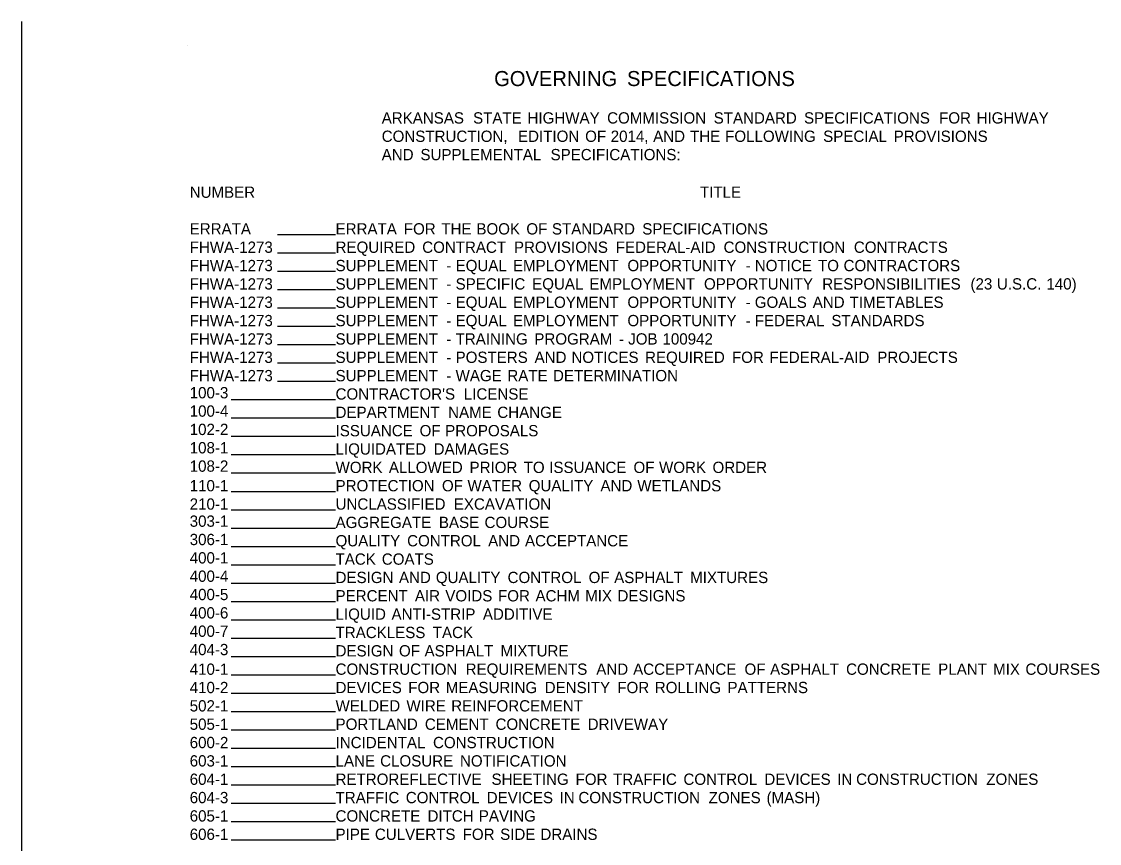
# Model space of a CAD drawing. Extents: x 1.5 to 33, y 0.6 to 21.4.
# Drawn here: x 1.52 to 15.26, y 10.94 to 21.42 of the extents above; entities that cross this region are included whole.
import ezdxf

# ---------------------------------------------------------------- set-up
doc = ezdxf.new("R2010")
doc.units = 0
doc.layers.add('Default', color=7, linetype='Continuous')

msp = doc.modelspace()

# ---------------------------------------------------------------- linework, layer by layer
at = {"layer": 'Default'}
for p, q in [((1.516, 21.423), (1.516, 0.577)), ((3.636, 21.112), (3.636, 21.112)), ((4.78, 18.707), (5.52, 18.707)), ((4.78, 18.473), (5.52, 18.473)), ((4.78, 18.239), (5.52, 18.239)), ((4.78, 18.005), (5.52, 18.005)), ((4.78, 17.771), (5.52, 17.771)), ((4.78, 17.537), (5.52, 17.537)), ((4.78, 17.303), (5.52, 17.303)), ((4.78, 17.069), (5.52, 17.069)), ((4.78, 16.835), (5.52, 16.835)), ((4.188, 16.601), (5.52, 16.601)), ((4.188, 16.367), (5.52, 16.367)), ((4.188, 16.133), (5.52, 16.133)), ((4.188, 15.899), (5.52, 15.899)), ((4.188, 15.665), (5.52, 15.665)), ((4.188, 15.431), (5.52, 15.431)), ((4.188, 15.197), (5.52, 15.197)), ((4.188, 14.963), (5.52, 14.963)), ((4.188, 14.729), (5.52, 14.729)), ((4.188, 14.495), (5.52, 14.495)), ((4.188, 14.261), (5.52, 14.261)), ((4.188, 14.027), (5.52, 14.027)), ((4.188, 13.793), (5.52, 13.793)), ((4.188, 13.559), (5.52, 13.559)), ((4.188, 13.325), (5.52, 13.325)), ((4.188, 13.091), (5.52, 13.091)), ((4.188, 12.857), (5.52, 12.857)), ((4.188, 12.623), (5.52, 12.623)), ((4.188, 12.389), (5.52, 12.389)), ((4.188, 12.155), (5.52, 12.155)), ((4.188, 11.921), (5.52, 11.921)), ((4.188, 11.687), (5.52, 11.687)), ((4.188, 11.453), (5.52, 11.453)), ((4.188, 11.219), (5.52, 11.219)), ((4.188, 10.985), (5.52, 10.985))]:
    msp.add_line(p, q, dxfattribs=at)

# ---------------------------------------------------------------- texts
for s, height, p in [('GOVERNING', 0.192, (7.542, 20.6)), (' SPECIFICATIONS', 0.192, (9.165, 20.6)), ('           ARKANSAS', 0.144, (5.52, 20.122)), (' STATE', 0.144, (7.22, 20.122)), (' HIGHWAY', 0.144, (7.914, 20.122)), (' COMMISSION', 0.144, (8.929, 20.122)), (' STANDARD', 0.144, (10.288, 20.122)), (' SPECIFICATIONS', 0.144, (11.44, 20.122)), (' FOR', 0.144, (13.162, 20.122)), (' HIGHWAY', 0.144, (13.64, 20.122)), ('           CONSTRUCTION,', 0.144, (5.52, 19.888)), (' EDITION', 0.144, (7.793, 19.888)), (' OF', 0.144, (8.649, 19.888)), (' 2014,', 0.144, (8.975, 19.888)), (' AND', 0.144, (9.516, 19.888)), (' THE', 0.144, (9.986, 19.888)), (' FOLLOWING', 0.144, (10.434, 19.888)), (' SPECIAL', 0.144, (11.684, 19.888)), (' PROVISIONS', 0.144, (12.583, 19.888)), ('           AND', 0.144, (5.52, 19.654)), (' SUPPLEMENTAL', 0.144, (6.549, 19.654)), (' SPECIFICATIONS:', 0.144, (8.208, 19.654)), ('NUMBER', 0.144, (3.66, 19.175)), ('TITLE', 0.144, (10.166, 19.175)), ('ERRATA', 0.144, (3.66, 18.707)), ('ERRATA', 0.144, (5.52, 18.707)), (' FOR', 0.144, (6.337, 18.707)), (' THE', 0.144, (6.815, 18.707)), (' BOOK', 0.144, (7.262, 18.707)), (' OF', 0.144, (7.899, 18.707)), (' STANDARD', 0.144, (8.225, 18.707)), (' SPECIFICATIONS', 0.144, (9.377, 18.707)), ('FHWA-1273', 0.144, (3.66, 18.473)), ('REQUIRED', 0.144, (5.52, 18.473)), (' CONTRACT', 0.144, (6.571, 18.473)), (' PROVISIONS', 0.144, (7.741, 18.473)), (' FEDERAL-AID', 0.144, (9.039, 18.473)), (' CONSTRUCTION', 0.144, (10.414, 18.473)), (' CONTRACTS', 0.144, (12.075, 18.473)), ('FHWA-1273', 0.144, (3.66, 18.239)), ('SUPPLEMENT', 0.144, (5.52, 18.239)), (' -', 0.144, (6.88, 18.239)), (' EQUAL', 0.144, (6.997, 18.239)), (' EMPLOYMENT', 0.144, (7.728, 18.239)), (' OPPORTUNITY', 0.144, (9.188, 18.239)), (' -', 0.144, (10.696, 18.239)), (' NOTICE', 0.144, (10.812, 18.239)), (' TO', 0.144, (11.618, 18.239)), (' CONTRACTORS', 0.144, (11.944, 18.239)), ('FHWA-1273', 0.144, (3.66, 18.005)), ('SUPPLEMENT', 0.144, (5.52, 18.005)), (' SPECIFIC', 0.144, (6.997, 18.005)), (' EQUAL', 0.144, (7.973, 18.005)), (' EMPLOYMENT', 0.144, (8.703, 18.005)), (' OPPORTUNITY', 0.144, (10.164, 18.005)), (' RESPONSIBILITIES', 0.144, (11.672, 18.005)), (' (23', 0.144, (13.562, 18.005)), (' U.S.C.', 0.144, (13.899, 18.005)), (' 140)', 0.144, (14.53, 18.005)), (' -', 0.144, (6.88, 18.005)), ('FHWA-1273', 0.144, (3.66, 17.771)), ('SUPPLEMENT', 0.144, (5.52, 17.771)), (' EQUAL', 0.144, (6.997, 17.771)), (' EMPLOYMENT', 0.144, (7.728, 17.771)), (' OPPORTUNITY', 0.144, (9.188, 17.771)), (' GOALS', 0.144, (10.812, 17.771)), (' AND', 0.144, (11.551, 17.771)), (' TIMETABLES', 0.144, (12.021, 17.771)), (' -', 0.144, (6.88, 17.771)), (' -', 0.144, (10.696, 17.771)), ('FHWA-1273', 0.144, (3.66, 17.537)), ('SUPPLEMENT', 0.144, (5.52, 17.537)), (' -', 0.144, (6.88, 17.537)), (' EQUAL', 0.144, (6.997, 17.537)), (' EMPLOYMENT', 0.144, (7.728, 17.537)), (' OPPORTUNITY', 0.144, (9.188, 17.537)), (' -', 0.144, (10.696, 17.537)), (' FEDERAL', 0.144, (10.812, 17.537)), (' STANDARDS', 0.144, (11.789, 17.537)), ('FHWA-1273', 0.144, (3.66, 17.303)), ('SUPPLEMENT', 0.144, (5.52, 17.303)), (' -', 0.144, (6.88, 17.303)), (' TRAINING', 0.144, (6.997, 17.303)), (' PROGRAM', 0.144, (8.001, 17.303)), (' -', 0.144, (9.082, 17.303)), (' JOB', 0.144, (9.198, 17.303)), (' 100942', 0.144, (9.635, 17.303)), ('FHWA-1273', 0.144, (3.66, 17.069)), ('SUPPLEMENT', 0.144, (5.52, 17.069)), (' POSTERS', 0.144, (6.997, 17.069)), (' AND', 0.144, (8.004, 17.069)), (' NOTICES', 0.144, (8.474, 17.069)), (' REQUIRED', 0.144, (9.413, 17.069)), (' FOR', 0.144, (10.521, 17.069)), (' FEDERAL-AID', 0.144, (10.999, 17.069)), (' PROJECTS', 0.144, (12.374, 17.069)), (' -', 0.144, (6.88, 17.069)), ('FHWA-1273', 0.144, (3.66, 16.835)), ('SUPPLEMENT', 0.144, (5.52, 16.835)), (' WAGE', 0.144, (6.997, 16.835)), (' RATE', 0.144, (7.657, 16.835)), (' DETERMINATION', 0.144, (8.239, 16.835)), (' -', 0.144, (6.88, 16.835)), ('100-3', 0.144, (3.66, 16.617)), ("CONTRACTOR'S", 0.144, (5.52, 16.601)), (' LICENSE', 0.144, (7.102, 16.601)), ('100-4', 0.144, (3.66, 16.383)), ('DEPARTMENT', 0.144, (5.52, 16.367)), (' NAME', 0.144, (6.902, 16.367)), (' CHANGE', 0.144, (7.529, 16.367)), ('102-2', 0.144, (3.66, 16.149)), ('ISSUANCE', 0.144, (5.52, 16.133)), (' OF', 0.144, (6.538, 16.133)), (' PROPOSALS', 0.144, (6.864, 16.133)), ('108-1', 0.144, (3.66, 15.915)), ('LIQUIDATED', 0.144, (5.52, 15.899)), (' DAMAGES', 0.144, (6.717, 15.899)), ('108-2', 0.144, (3.66, 15.681)), ('WORK', 0.144, (5.52, 15.665)), (' ALLOWED', 0.144, (6.146, 15.665)), (' PRIOR', 0.144, (7.175, 15.665)), (' TO', 0.144, (7.865, 15.665)), (' ISSUANCE', 0.144, (8.191, 15.665)), (' OF', 0.144, (9.265, 15.665)), (' WORK', 0.144, (9.591, 15.665)), (' ORDER', 0.144, (10.273, 15.665)), ('110-1', 0.144, (3.66, 15.431)), ('PROTECTION', 0.144, (5.52, 15.431)), (' OF', 0.144, (6.823, 15.431)), (' WATER', 0.144, (7.149, 15.431)), (' QUALITY', 0.144, (7.929, 15.431)), (' AND', 0.144, (8.844, 15.431)), (' WETLANDS', 0.144, (9.314, 15.431)), ('210-1', 0.144, (3.66, 15.197)), ('UNCLASSIFIED', 0.144, (5.52, 15.197)), (' EXCAVATION', 0.144, (6.974, 15.197)), ('303-1', 0.144, (3.66, 14.979)), ('AGGREGATE', 0.144, (5.52, 14.963)), (' BASE', 0.144, (6.784, 14.963)), (' COURSE', 0.144, (7.366, 14.963)), ('306-1', 0.144, (3.66, 14.745)), ('QUALITY', 0.144, (5.52, 14.729)), (' CONTROL', 0.144, (6.379, 14.729)), (' AND', 0.144, (7.412, 14.729)), (' ACCEPTANCE', 0.144, (7.882, 14.729)), ('400-1', 0.144, (3.66, 14.511)), ('TACK', 0.144, (5.52, 14.495)), (' COATS', 0.144, (6.056, 14.495)), ('400-4', 0.144, (3.66, 14.277)), ('DESIGN', 0.144, (5.52, 14.261)), (' AND', 0.144, (6.275, 14.261)), (' QUALITY', 0.144, (6.745, 14.261)), (' CONTROL', 0.144, (7.66, 14.261)), (' OF', 0.144, (8.693, 14.261)), (' ASPHALT', 0.144, (9.019, 14.261)), (' MIXTURES', 0.144, (9.988, 14.261)), ('400-5', 0.144, (3.66, 14.043)), ('PERCENT', 0.144, (5.52, 14.027)), (' AIR', 0.144, (6.478, 14.027)), (' VOIDS', 0.144, (6.866, 14.027)), (' FOR', 0.144, (7.538, 14.027)), (' ACHM', 0.144, (8.016, 14.027)), (' MIX', 0.144, (8.649, 14.027)), (' DESIGNS', 0.144, (9.061, 14.027)), ('400-6', 0.144, (3.66, 13.809)), ('LIQUID', 0.144, (5.52, 13.793)), (' ANTI-STRIP', 0.144, (6.18, 13.793)), (' ADDITIVE', 0.144, (7.345, 13.793)), ('400-7', 0.144, (3.66, 13.575)), ('TRACKLESS', 0.144, (5.52, 13.559)), (' TACK', 0.144, (6.706, 13.559)), ('404-3', 0.144, (3.66, 13.341)), ('DESIGN', 0.144, (5.52, 13.325)), (' OF', 0.144, (6.275, 13.325)), (' ASPHALT', 0.144, (6.601, 13.325)), (' MIXTURE', 0.144, (7.57, 13.325)), ('410-1', 0.144, (3.66, 13.091)), ('CONSTRUCTION', 0.144, (5.52, 13.091)), (' REQUIREMENTS', 0.144, (7.125, 13.091)), (' AND', 0.144, (8.791, 13.091)), (' ACCEPTANCE', 0.144, (9.261, 13.091)), (' OF', 0.144, (10.681, 13.091)), (' ASPHALT', 0.144, (11.007, 13.091)), (' CONCRETE', 0.144, (11.976, 13.091)), (' PLANT', 0.144, (13.151, 13.091)), (' MIX', 0.144, (13.851, 13.091)), (' COURSES', 0.144, (14.263, 13.091)), ('410-2', 0.144, (3.66, 12.857)), ('DEVICES', 0.144, (5.52, 12.857)), (' FOR', 0.144, (6.393, 12.857)), (' MEASURING', 0.144, (6.871, 12.857)), (' DENSITY', 0.144, (8.133, 12.857)), (' FOR', 0.144, (9.059, 12.857)), (' ROLLING', 0.144, (9.537, 12.857)), (' PATTERNS', 0.144, (10.464, 12.857)), ('502-1', 0.144, (3.66, 12.623)), ('WELDED', 0.144, (5.52, 12.623)), (' WIRE', 0.144, (6.37, 12.623)), (' REINFORCEMENT', 0.144, (6.941, 12.623)), ('505-1', 0.144, (3.66, 12.389)), ('PORTLAND', 0.144, (5.52, 12.389)), (' CEMENT', 0.144, (6.605, 12.389)), (' CONCRETE', 0.144, (7.506, 12.389)), (' DRIVEWAY', 0.144, (8.681, 12.389)), ('600-2', 0.144, (3.66, 12.155)), ('INCIDENTAL', 0.144, (5.52, 12.155)), (' CONSTRUCTION', 0.144, (6.709, 12.155)), ('603-1', 0.144, (3.66, 11.921)), ('LANE', 0.144, (5.52, 11.921)), (' CLOSURE', 0.144, (6.035, 11.921)), (' NOTIFICATION', 0.144, (7.053, 11.921)), ('604-1', 0.144, (3.66, 11.687)), ('RETROREFLECTIVE', 0.144, (5.52, 11.687)), (' SHEETING', 0.144, (7.455, 11.687)), (' FOR', 0.144, (8.527, 11.687)), (' TRAFFIC', 0.144, (9.005, 11.687)), (' CONTROL', 0.144, (9.902, 11.687)), (' DEVICES', 0.144, (10.934, 11.687)), (' IN', 0.144, (11.863, 11.687)), (' CONSTRUCTION', 0.144, (12.104, 11.687)), (' ZONES', 0.144, (13.764, 11.687)), ('604-3', 0.144, (3.66, 11.453)), ('TRAFFIC', 0.144, (5.52, 11.453)), (' CONTROL', 0.144, (6.362, 11.453)), (' DEVICES', 0.144, (7.394, 11.453)), (' IN', 0.144, (8.323, 11.453)), (' CONSTRUCTION', 0.144, (8.563, 11.453)), (' ZONES', 0.144, (10.224, 11.453)), (' (MASH)', 0.144, (10.962, 11.453)), ('605-1', 0.144, (3.66, 11.219)), ('CONCRETE', 0.144, (5.52, 11.219)), (' DITCH', 0.144, (6.639, 11.219)), (' PAVING', 0.144, (7.293, 11.219)), ('606-1', 0.144, (3.66, 10.985)), ('PIPE', 0.144, (5.52, 10.985)), (' CULVERTS', 0.144, (5.968, 10.985)), (' FOR', 0.144, (7.087, 10.985)), (' SIDE', 0.144, (7.565, 10.985)), (' DRAINS', 0.144, (8.079, 10.985))]:
    msp.add_text(s, height=height, dxfattribs=at).set_placement(p)

doc.saveas('drawing.dxf')
